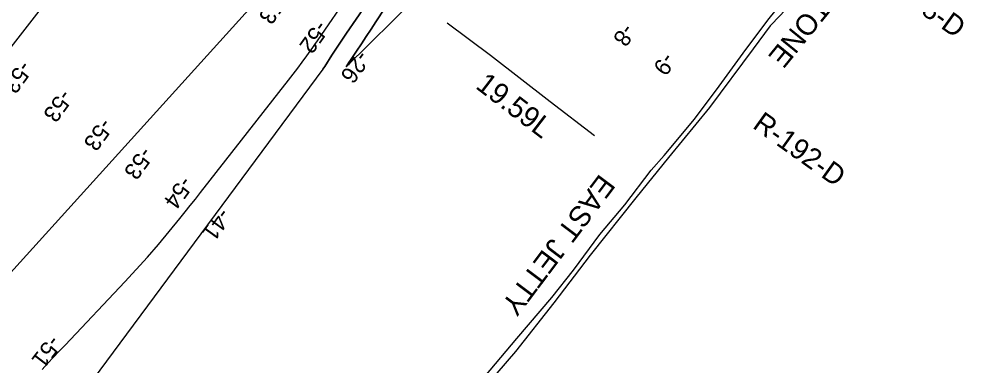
# Model space of a CAD drawing. Extents: x 3879599 to 3900814, y 146526 to 168888.
# Drawn here: x 3891140 to 3893070, y 154174 to 154874 of the extents above; entities that cross this region are included whole.
import ezdxf

# ---------------------------------------------------------------- set-up
doc = ezdxf.new("R2010")
doc.units = 0
for name, color, linetype in [('V-LEVE-TOET', 7, 'Continuous'), ('V-RIVR-JETY', 7, 'Continuous'), ('V-RIVR-RANG', 7, 'Continuous'), ('V-RIVR-RANG-IDEN', 7, 'Continuous'), ('V-STRM-FMON', 7, 'Continuous'), ('V-TOPO-DPTH', 7, 'Continuous'), ('V-TOPO-MAJR', 7, 'Continuous'), ('V-TOPO-MINR', 7, 'Continuous')]:
    doc.layers.add(name, color=color, linetype=linetype)

msp = doc.modelspace()

# ---------------------------------------------------------------- linework, layer by layer
at = {"layer": 'V-LEVE-TOET'}
msp.add_lwpolyline([(3892004.8, 154866.9), (3892092.3, 154801.8), (3892212.5, 154707.9), (3892302.4, 154639.2)], dxfattribs=at)
at = {"layer": 'V-RIVR-JETY'}
for points in [[(3893401.2, 155761.7), (3893383.4, 155735.7), (3893336, 155676), (3893276.6, 155604), (3893212.2, 155535.7), (3893158.9, 155467.2), (3893086, 155378.3), (3893009.8, 155289.4), (3892931, 155195.2), (3892859.8, 155101.4), (3892769.8, 154985), (3892723.9, 154932.9), (3892677.1, 154881.5), (3892656.9, 154860.4), (3892622.6, 154814.1), (3892534.6, 154695.5), (3892451.7, 154594.8), (3892385.6, 154513.6), (3892293.4, 154397.6), (3892219.9, 154301.1), (3892142.7, 154203.1), (3892063.5, 154110.7)], [(3892081.1, 154152.3), (3892145.8, 154229.3), (3892216, 154312.1), (3892259.7, 154367.2), (3892313.4, 154439.5), (3892363.4, 154498.9), (3892416.8, 154568.9), (3892443.3, 154598.8), (3892504.6, 154672), (3892553.8, 154738.6), (3892607.8, 154813.2), (3892655.2, 154875.2), (3892675, 154900.1), (3892689.2, 154915.8), (3892717.3, 154942.3), (3892740.1, 154967.2), (3892776.7, 155012.8), (3892836, 155087.1), (3892895.7, 155165.6), (3892968.1, 155257.8), (3893000.6, 155300.3), (3893016.3, 155318.7), (3893097, 155409.6)]]:
    msp.add_lwpolyline(points, dxfattribs=at)
at = {"layer": 'V-RIVR-RANG'}
msp.add_lwpolyline([(3887950.4, 150855.4), (3895383.9, 159071.9)], dxfattribs=at)
at = {"layer": 'V-TOPO-DPTH'}
msp.add_line((3892047.3, 155021.7), (3891801.2, 154777.8), dxfattribs=at)
for points in [[(3891801.2, 154777.8), (3891802.2, 154779.7), (3891806.6, 154786.7), (3891811.1, 154793.7), (3891821.7, 154809.5), (3891831.6, 154824.2), (3891841.5, 154839), (3891851.4, 154853.9), (3891861.1, 154868.8), (3891967.4, 155031.1)], [(3891967.4, 155031.1), (3891861.1, 154868.8), (3891851.4, 154853.9), (3891841.5, 154839), (3891831.6, 154824.2), (3891821.7, 154809.5), (3891811.1, 154793.7), (3891806.6, 154786.7), (3891802.2, 154779.7), (3891801.2, 154777.8)], [(3891753.9, 154772.9), (3891757.6, 154778.7), (3891772.1, 154801.2), (3891786.9, 154823.5), (3891801.8, 154845.7), (3891859.9, 154931.1)], [(3891859.9, 154931.1), (3891801.8, 154845.7), (3891786.9, 154823.5), (3891772.1, 154801.2), (3891757.6, 154778.7), (3891753.9, 154772.9)], [(3891753.9, 154772.9), (3891153.5, 153962.5)]]:
    msp.add_lwpolyline(points, dxfattribs=at)
at = {"layer": 'V-TOPO-MAJR'}
for points in [[(3891234.7, 154960.9), (3891123.9, 154817.7)], [(3891187.2, 154166.9), (3891198.6, 154179.3), (3891210.1, 154191.6), (3891221.6, 154203.9), (3891233.2, 154216.1), (3891354.1, 154343.6), (3891377.1, 154368.4), (3891399.7, 154393.6), (3891421.8, 154419.3), (3891443.5, 154445.2), (3891465.2, 154471.8), (3891475.7, 154484.8), (3891486.2, 154497.8), (3891496.6, 154510.9), (3891506.9, 154524), (3891684.5, 154750.9), (3891693.9, 154763), (3891703.1, 154775.2), (3891712.3, 154787.5), (3891721.3, 154799.8), (3891733.9, 154817.2), (3891736.5, 154821), (3891739.2, 154824.7), (3891741.8, 154828.5), (3891744.4, 154832.3), (3891808.1, 154926.1)]]:
    msp.add_lwpolyline(points, dxfattribs=at)
at = {"layer": 'V-TOPO-MINR'}
for points in [[(3891801.2, 154777.8), (3891802.2, 154779.7), (3891806.6, 154786.7), (3891811.1, 154793.7), (3891821.7, 154809.5), (3891831.6, 154824.2), (3891841.5, 154839), (3891851.4, 154853.9), (3891861.1, 154868.8), (3891967.4, 155031.1)], [(3891753.9, 154772.9), (3891757.6, 154778.7), (3891772.1, 154801.2), (3891786.9, 154823.5), (3891801.8, 154845.7), (3891859.9, 154931.1)]]:
    msp.add_lwpolyline(points, dxfattribs=at)

# ---------------------------------------------------------------- texts
at = {"layer": 'V-RIVR-JETY'}
for s, rotation, p in [('STONE', 230.9182, (3892773.5, 154949.3)), ('EAST JETTY', 232.9925, (3892313.2, 154563.6))]:
    msp.add_text(s, height=42, rotation=rotation, dxfattribs=at).set_placement(p)
at = {"layer": 'V-RIVR-RANG'}
for s, rotation, p in [('-53', 234.4529, (3891660.3, 154932.5)), ('-52', 234.4529, (3891742.3, 154873.6)), ('-8', 234.3083, (3892361.4, 154867.5)), ('-26', 234.4529, (3891825.4, 154813.2)), ('-9', 234.3083, (3892442.6, 154809.1)), ('-53', 234.0789, (3891144.1, 154792.7)), ('-53', 234.0789, (3891225.6, 154734.7)), ('-53', 234.0789, (3891307.1, 154676.7)), ('-53', 234.0789, (3891388.5, 154618.7)), ('-54', 234.0789, (3891469, 154559.4)), ('-41', 234.0789, (3891545.8, 154495.1)), ('-51', 232.6215, (3891203.1, 154238.1))]:
    msp.add_text(s, height=33.5, rotation=rotation, dxfattribs=at).set_placement(p)
at = {"layer": 'V-RIVR-RANG-IDEN'}
for s, rotation, p in [('R-188-D', 324.2083, (3892862, 154956.9)), ('R-192-D', 324.4528, (3892619.5, 154655.8))]:
    msp.add_text(s, height=41.5, rotation=rotation, dxfattribs=at).set_placement(p)
at = {"layer": 'V-STRM-FMON'}
msp.add_text('19.59L', height=42, rotation=322.4812, dxfattribs=at).set_placement((3892060.2, 154736))

doc.saveas('drawing.dxf')
